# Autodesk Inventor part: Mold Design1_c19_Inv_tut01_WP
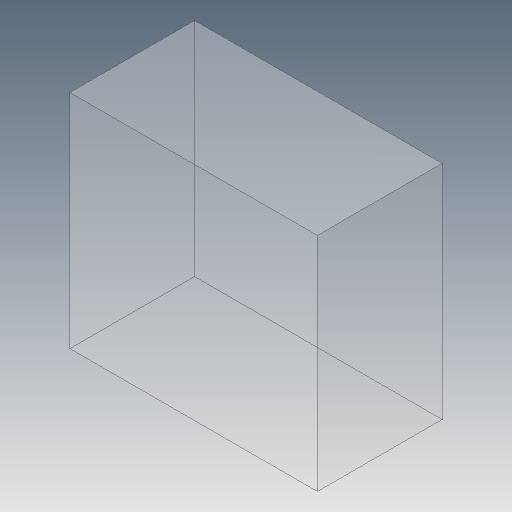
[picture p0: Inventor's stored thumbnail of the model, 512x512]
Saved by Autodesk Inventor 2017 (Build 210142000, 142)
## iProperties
Created: 2016-07
Part Number: Mold Design1_c19_Inv_tut01_WP
Material: Generic
Document SubType Name: Modeling
Designer: Sandeep
Density: 1 g/cm^3
Appearance: Default
Author: Sandeep
d0: -157.500 mm
d1: 312.500 mm
d2: 312.500 mm
d3: 280.000 mm
d4: 280.000 mm
d5: 315.000 mm
d6: 0.00 deg
Xmin: -312.500 mm
Ymin: -280.000 mm
Zmin: -157.500 mm
Xmax: 312.500 mm
Ymax: 280.000 mm
Zmax: 157.500 mm
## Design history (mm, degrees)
sketch "Sketch1"
  geometry: L1 (-312.5, 280)-(312.5, 280); L2 (312.5, 280)-(312.5, -280); L3 (312.5, -280)-(-312.5, -280); L4 (-312.5, -280)-(-312.5, 280); 1 further point
  constraints: 8 end point, 2 parallel, 1 horizontal, 1 perpendicular, 1 other
  dimensions: "d1" = 312.5 distance from line of L4 point (0, 0) (= -Xmin); "d2" = 312.5 distance from line of L2 point (0, 0) (= Xmax); "d3" = 280 distance from line of L3 point (0, 0) (= -Ymin); "d4" = 280 distance from line of L1 point (0, 0) (= Ymax)
extrude "Extrusion1" join sketch "Sketch1" distance "d5" = 315 (= Zmax - Zmin); taper "d6" = 0 deg
body "Solid1"
other parameters: "Xmin" = -312.5 [user parameter; used in 1 equation term], "Ymin" = -280 [user parameter; used in 1 equation term], "Zmin" = -157.5 [user parameter; used in 1 equation term], "Xmax" = 312.5 [user parameter; used in 1 equation term], "Ymax" = 280 [user parameter; used in 1 equation term], "Zmax" = 157.5 [user parameter; used in 1 equation term], "d0" = -157.5
